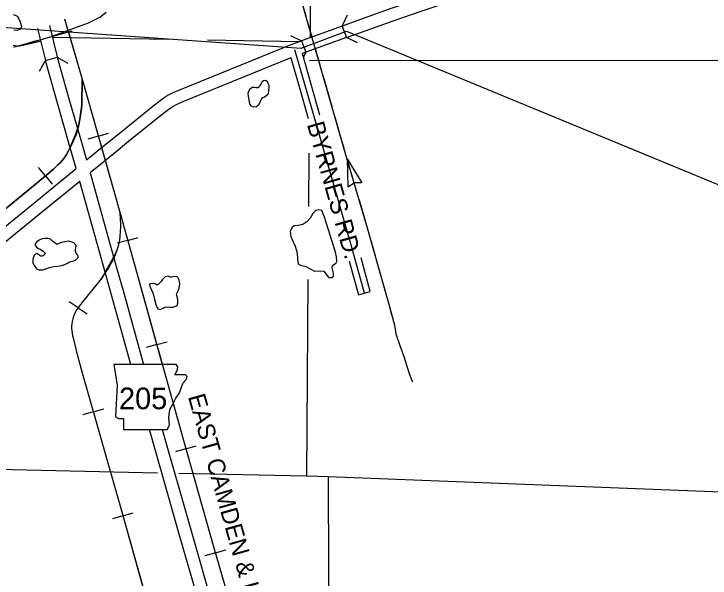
# Model space of a CAD drawing. Extents: x 1373094 to 1376427, y 1168361 to 1170494.
# Drawn here: x 1374665 to 1375232, y 1168831 to 1169290 of the extents above; entities that cross this region are included whole.
import ezdxf

# ---------------------------------------------------------------- set-up
doc = ezdxf.new("R2010")
doc.units = 0
for name, color, linetype in [('R_Axis', 7, 'Continuous'), ('R_Dimension', 7, 'Continuous'), ('R_Draft', 7, 'Continuous'), ('R_Water Annot', 7, 'Continuous')]:
    doc.layers.add(name, color=color, linetype=linetype)

msp = doc.modelspace()

# ---------------------------------------------------------------- linework, layer by layer
at = {"layer": 'R_Axis'}
for p, q in [((1374899.43, 1169267.75), (1374902.83, 1169258.34)), ((1374733.98, 1169190.12), (1374742.45, 1169192.52)), ((1374733.98, 1169190.12), (1374725.51, 1169187.73)), ((1374936.39, 1169171.79), (1374936.99, 1169148.91)), ((1374936.39, 1169171.79), (1374948.35, 1169152.28)), ((1374690.97, 1169157.88), (1374685.36, 1169164.66)), ((1374690.97, 1169157.88), (1374696.58, 1169151.1)), ((1374936.99, 1169148.91), (1374942.18, 1169152.1)), ((1374948.35, 1169152.28), (1374942.26, 1169152.12)), ((1374757.89, 1169105.43), (1374766.36, 1169107.81)), ((1374757.89, 1169105.43), (1374749.41, 1169103.06)), ((1374945.68, 1169061.27), (1374955.32, 1169063.92)), ((1374717.59, 1169050.61), (1374710.23, 1169055.44)), ((1374717.59, 1169050.61), (1374724.95, 1169045.79)), ((1374781.55, 1169020.67), (1374790.03, 1169023.04)), ((1374781.55, 1169020.67), (1374773.07, 1169018.31)), ((1374729.98, 1168966.05), (1374721.51, 1168963.64)), ((1374729.98, 1168966.05), (1374738.44, 1168968.45)), ((1374805.23, 1168935.92), (1374796.76, 1168933.52)), ((1374805.23, 1168935.92), (1374813.69, 1168938.32)), ((1374754.01, 1168881.4), (1374745.54, 1168879.01)), ((1374754.01, 1168881.4), (1374762.48, 1168883.78)), ((1374829.28, 1168851.27), (1374820.83, 1168848.82)), ((1374829.28, 1168851.27), (1374837.73, 1168853.72))]:
    msp.add_line(p, q, dxfattribs=at)
for points in [[(1374906.66, 1169411.1), (1374906.32, 1169269.99)], [(1374990.01, 1168990.5), (1374989.46, 1168991.36), (1374987.1, 1168997), (1374982.47, 1169011.56), (1374979.67, 1169019.8), (1374976.73, 1169028.3), (1374975.26, 1169036.23), (1374970.65, 1169053.39), (1374953.09, 1169115.44), (1374934.6, 1169177.81), (1374897.2, 1169307.95), (1374877.82, 1169376.24)], [(1375047.9, 1169319.87), (1374993.51, 1169301.24), (1374970.66, 1169293.33), (1374957.07, 1169288.57), (1374932.54, 1169279.71)], [(1374935.94, 1169270.3), (1374960.42, 1169279.14), (1374973.95, 1169283.89), (1374996.76, 1169291.79), (1375050.66, 1169310.25)], [(1374903.02, 1169287.69), (1374897.44, 1169307.09)], [(1374664.69, 1169289.18), (1374666.29, 1169288.66), (1374668.02, 1169287.73), (1374669.1, 1169286.14), (1374670.18, 1169283.61), (1374671.12, 1169281.48), (1374671.67, 1169279.08), (1374670.62, 1169277.07), (1374667.97, 1169276.12), (1374665.31, 1169276.24)], [(1374696.62, 1169271.37), (1374720.05, 1169280.03), (1374726.15, 1169282.2), (1374730.53, 1169284.49), (1374735.16, 1169286.79), (1374740.32, 1169290.96)], [(1374932.54, 1169279.71), (1374936.79, 1169288.76)], [(1374706.56, 1169285.51), (1374720.89, 1169236.39), (1374740.58, 1169166.79)], [(1374684.6, 1169277.69), (1374690.98, 1169251.63)], [(1374694.32, 1169280.16), (1374700.54, 1169254.61)], [(1374932.54, 1169279.71), (1374899.43, 1169267.75)], [(1374907.88, 1169270.8), (1374906.23, 1169276.52)], [(1374932.54, 1169279.71), (1374935.94, 1169270.3)], [(1374712.44, 1169275.44), (1374668.72, 1169263.46)], [(1374696.6, 1169270.79), (1374791.4, 1169269.11)], [(1374709.71, 1169274.71), (1374720.89, 1169236.39), (1374751.47, 1169128.32), (1374762.3, 1169089.68), (1374802.97, 1168943.89), (1374828.09, 1168855.37), (1374852.96, 1168769.72), (1374869.21, 1168714.06), (1374879.23, 1168680.09)], [(1374890.38, 1169272), (1374899.43, 1169267.75)], [(1374935.94, 1169270.3), (1374902.83, 1169258.34)], [(1374944.99, 1169266.05), (1374935.94, 1169270.3)], [(1374664.72, 1169264.08), (1374668.85, 1169263.44), (1374686.71, 1169267.52)], [(1374683.65, 1169267.55), (1374668.72, 1169263.46), (1374665.76, 1169262.65)], [(1374790.07, 1169223.1), (1374794.94, 1169225.57), (1374799.42, 1169227.47), (1374892.2, 1169265.14), (1374899.43, 1169267.75)], [(1374822.99, 1169268.55), (1374897.35, 1169267.23)], [(1374668.72, 1169263.46), (1374665.04, 1169262.45)], [(1374950.5, 1169062.6), (1374940.01, 1169100.71), (1374910.6, 1169202.25), (1374894.02, 1169260.48)], [(1374914.46, 1169247.89), (1374910.64, 1169261.17)], [(1374690.95, 1169251.75), (1374700.57, 1169254.48)], [(1374700.57, 1169254.48), (1374709.31, 1169249.61)], [(1374700.57, 1169254.48), (1374710.45, 1169219.73), (1374720.35, 1169185.34), (1374724.42, 1169170.81)], [(1374890.74, 1169253.75), (1374803.24, 1169218.23), (1374799.1, 1169216.48), (1374795.7, 1169214.79)], [(1374890.74, 1169253.75), (1374897.37, 1169230.46)], [(1374902.83, 1169258.34), (1374900.11, 1169257.36)], [(1374906.99, 1169233.2), (1374900.11, 1169257.36)], [(1374902.83, 1169258.34), (1374900.96, 1169254.36)], [(1374686.08, 1169243.02), (1374690.95, 1169251.75)], [(1374715.97, 1169163.91), (1374710.73, 1169182.61), (1374700.83, 1169216.98), (1374690.95, 1169251.75)], [(1374905.85, 1169251.57), (1375238.19, 1169252.01), (1375330.82, 1169249.65)], [(1374565.5, 1169055.01), (1374684.25, 1169152.32), (1374693.96, 1169160.35), (1374697.61, 1169163.43), (1374701.24, 1169166.75), (1374702.96, 1169168.49), (1374704.86, 1169170.54), (1374706.2, 1169172.23), (1374708.15, 1169175.22), (1374709.83, 1169178.3), (1374711.96, 1169182.54), (1374713.35, 1169185.4), (1374714.52, 1169187.99), (1374715.95, 1169191.55), (1374716.79, 1169194.11), (1374717.6, 1169197.04), (1374718.18, 1169199.53), (1374718.77, 1169202.46), (1374719.36, 1169205.68), (1374719.94, 1169209.63), (1374720.37, 1169213.11), (1374720.6, 1169215.54), (1374720.89, 1169236.39)], [(1374720.89, 1169236.39), (1374720.6, 1169215.54), (1374720.37, 1169213.11), (1374719.94, 1169209.63), (1374719.36, 1169205.68), (1374718.77, 1169202.46), (1374718.18, 1169199.53), (1374717.6, 1169197.04), (1374716.79, 1169194.11), (1374715.95, 1169191.55), (1374714.52, 1169187.99), (1374713.35, 1169185.4), (1374711.96, 1169182.54), (1374709.83, 1169178.3), (1374708.15, 1169175.22), (1374706.2, 1169172.23), (1374704.86, 1169170.54), (1374702.96, 1169168.49), (1374701.24, 1169166.75), (1374697.61, 1169163.43), (1374693.96, 1169160.35), (1374684.25, 1169152.32), (1374565.5, 1169055.01)], [(1374720.89, 1169236.39), (1374720.6, 1169215.54), (1374720.37, 1169213.11), (1374719.94, 1169209.63), (1374719.36, 1169205.68), (1374718.82, 1169202.71)], [(1374924.18, 1169214.06), (1374916.89, 1169239.43)], [(1374872.35, 1169224.74), (1374872.76, 1169227.07), (1374872.91, 1169230.22), (1374872.95, 1169231.42), (1374872.26, 1169233.01), (1374871.57, 1169234.4), (1374870.29, 1169235.45), (1374868.5, 1169235.09), (1374866.99, 1169234), (1374866.4, 1169233.12), (1374865.37, 1169231.37), (1374864.92, 1169230.29), (1374863.87, 1169229.34), (1374862.27, 1169229.51), (1374861.07, 1169229.83), (1374859.54, 1169229.81), (1374857.3, 1169228.5), (1374856.14, 1169226.35), (1374855.69, 1169224.87), (1374856.06, 1169222.8), (1374856.45, 1169219.74), (1374856.68, 1169217.74), (1374857.31, 1169215.88), (1374858.19, 1169214.82), (1374860.6, 1169213.92), (1374862.8, 1169214.16), (1374864.89, 1169216.13), (1374865.85, 1169218.55), (1374866.69, 1169220.23), (1374867.8, 1169221.52), (1374868.59, 1169221.93), (1374870.04, 1169222.82), (1374871.88, 1169224.25), (1374872.35, 1169224.74)], [(1374897.37, 1169230.46), (1374904.75, 1169204.55)], [(1374914.36, 1169207.33), (1374906.99, 1169233.2)], [(1374724.42, 1169170.81), (1374740.53, 1169183.95), (1374752.34, 1169193.55), (1374778.37, 1169214.5), (1374780.84, 1169216.39), (1374785.5, 1169220), (1374788.48, 1169222.05), (1374790.36, 1169223.26)], [(1374795.38, 1169214.61), (1374794.02, 1169213.73), (1374791.41, 1169211.93), (1374786.94, 1169208.46), (1374784.54, 1169206.63), (1374758.63, 1169185.77), (1374746.84, 1169176.2), (1374727.37, 1169160.3)], [(1374718.82, 1169202.71), (1374717.69, 1169198.36), (1374715.09, 1169191.07), (1374712.88, 1169185.22), (1374710.15, 1169178.84), (1374708.15, 1169175.22), (1374706.2, 1169172.23), (1374704.86, 1169170.54), (1374702.96, 1169168.49), (1374701.24, 1169166.75), (1374697.61, 1169163.43), (1374693.96, 1169160.35), (1374684.25, 1169152.32), (1374565.5, 1169055.01), (1374470.65, 1168977.12), (1374440.83, 1168952.74)], [(1374930.26, 1169192.92), (1374926.61, 1169205.6)], [(1374933.91, 1169180.23), (1374930.26, 1169192.92)], [(1374905.32, 1169176.44), (1374905.02, 1169132.9)], [(1374943.89, 1169146.47), (1374936.39, 1169171.79)], [(1374540.38, 1169020.57), (1374624.4, 1169089.36), (1374681.19, 1169135.53), (1374715.97, 1169163.91)], [(1374740.58, 1169166.79), (1374751.47, 1169128.32), (1374762.3, 1169089.68), (1374786.05, 1169004.54)], [(1374727.37, 1169160.3), (1374749.24, 1169082.3), (1374754.2, 1169064.61), (1374770.91, 1169004.55)], [(1374718.92, 1169153.41), (1374687.5, 1169127.78), (1374630.73, 1169081.61), (1374546.71, 1169012.83)], [(1374760.52, 1169004.55), (1374744.57, 1169061.92), (1374739.62, 1169079.6), (1374718.92, 1169153.41)], [(1374953.86, 1169112.72), (1374953.09, 1169115.44), (1374946.39, 1169138.04)], [(1374927.86, 1169087.38), (1374927.95, 1169088.44), (1374927.69, 1169091.98), (1374926.89, 1169095.97), (1374917.95, 1169124.42), (1374915.8, 1169129.8), (1374913.53, 1169130.17), (1374910.95, 1169129.59), (1374908.59, 1169127.42), (1374906.26, 1169123.44), (1374903.71, 1169120.6), (1374900.42, 1169118.27), (1374896.57, 1169117.54), (1374893.45, 1169117.16), (1374891.35, 1169115.59), (1374890.13, 1169112.7), (1374890.6, 1169108.5), (1374892.26, 1169104.85), (1374894.2, 1169100.74), (1374895.68, 1169095.42), (1374896.18, 1169089.95), (1374896.64, 1169086.28), (1374898.65, 1169085.25), (1374902.86, 1169084.24), (1374906.82, 1169082.1), (1374909.85, 1169080.28), (1374913.64, 1169080.67), (1374917.43, 1169080.53), (1374919.47, 1169077.89), (1374919.82, 1169077.16), (1374920.97, 1169075.71), (1374921.58, 1169075.38), (1374924.04, 1169075.29), (1374924.96, 1169075.97), (1374925.42, 1169076.31), (1374925.26, 1169078.31), (1374925.03, 1169079.98), (1374924.6, 1169081.84), (1374924.3, 1169083.64), (1374924.48, 1169084.58), (1374925.46, 1169085.66), (1374926.32, 1169086.28), (1374927.17, 1169086.83), (1374927.86, 1169087.38)], [(1374751.47, 1169128.32), (1374751.93, 1169122.31), (1374752.05, 1169118.61), (1374752.05, 1169116.32), (1374751.66, 1169108.88), (1374751.29, 1169105.91), (1374750.83, 1169103.06), (1374750.29, 1169100.74), (1374749.38, 1169098.16), (1374748.68, 1169096.21), (1374747.73, 1169093.79), (1374746, 1169089.76), (1374744.58, 1169087.13), (1374742.25, 1169083.15), (1374740.69, 1169080.66), (1374735.37, 1169072.69), (1374720.24, 1169054.29), (1374718.1, 1169051.38), (1374716.07, 1169048.3), (1374715.25, 1169046.89), (1374714.66, 1169045.65), (1374713.9, 1169043.48), (1374713.31, 1169041.54), (1374712.84, 1169039.42), (1374712.54, 1169037.67), (1374712.37, 1169035.72), (1374712.33, 1169033.92), (1374712.43, 1169032.07), (1374712.66, 1169030.19), (1374713.1, 1169027.86), (1374713.46, 1169026.19), (1374716.39, 1169014.75), (1374721, 1168997.65), (1374753.05, 1168884.79), (1374789.66, 1168754.64)], [(1374751.47, 1169128.32), (1374751.93, 1169122.31), (1374752.05, 1169118.61), (1374752.05, 1169116.32), (1374751.66, 1169108.88), (1374751.29, 1169105.91), (1374750.83, 1169103.06), (1374750.29, 1169100.74), (1374749.38, 1169098.16), (1374748.75, 1169096.4)], [(1374717.19, 1169093.64), (1374716.98, 1169093.97), (1374716.1, 1169095.16), (1374715.61, 1169096.42), (1374715.52, 1169097.76), (1374715.89, 1169099.3), (1374715.93, 1169101.17), (1374715.51, 1169102.17), (1374714.16, 1169103.41), (1374712.82, 1169103.99), (1374709.88, 1169104.68), (1374706.89, 1169104.3), (1374704.17, 1169103.66), (1374702.06, 1169102.76), (1374700.41, 1169102.2), (1374698.86, 1169103.04), (1374696.9, 1169104.68), (1374695.14, 1169106.52), (1374692.94, 1169107.09), (1374690.41, 1169107.05), (1374688.42, 1169106.62), (1374686.04, 1169105.65), (1374684.06, 1169104.35), (1374682.56, 1169102.59), (1374682.58, 1169101.45), (1374683.95, 1169099.54), (1374685.42, 1169098.76), (1374687.17, 1169097.98), (1374689.25, 1169096.75), (1374690.13, 1169095.96), (1374690.75, 1169094.9), (1374690.49, 1169094.09), (1374689.58, 1169093.08), (1374688.46, 1169092.53), (1374687.39, 1169092.58), (1374686.58, 1169093.23), (1374684.1, 1169094.66), (1374682.97, 1169094.18), (1374682.12, 1169093.3), (1374681.15, 1169091.61), (1374680.72, 1169089.4), (1374680.89, 1169087.53), (1374681.79, 1169085.07), (1374683.09, 1169083.02), (1374683.9, 1169082.37), (1374685.65, 1169081.53), (1374686.92, 1169081.35), (1374688.98, 1169081.45), (1374692.09, 1169082.43), (1374694.4, 1169083.47), (1374697.65, 1169084.32), (1374700.84, 1169084.5), (1374704.09, 1169085.09), (1374706.94, 1169085.93), (1374708.91, 1169087.03), (1374710.69, 1169088), (1374713.81, 1169088.78), (1374715.4, 1169089.47), (1374716.31, 1169090.22), (1374717.23, 1169091.1), (1374717.62, 1169091.44), (1374717.61, 1169092.38), (1374717.4, 1169093.04), (1374717.19, 1169093.64)], [(1374963.44, 1169078.85), (1374956.26, 1169104.25)], [(1374748.75, 1169096.4), (1374744.37, 1169088.17), (1374740.52, 1169081.1), (1374737.42, 1169075.64), (1374736.35, 1169073.93), (1374735.37, 1169072.69), (1374720.24, 1169054.29), (1374718.1, 1169051.38), (1374716.07, 1169048.3), (1374715.25, 1169046.89), (1374714.66, 1169045.65), (1374713.9, 1169043.48), (1374713.31, 1169041.54), (1374712.84, 1169039.42), (1374712.54, 1169037.67), (1374712.37, 1169035.72), (1374712.33, 1169033.92), (1374712.43, 1169032.07), (1374712.66, 1169030.19), (1374713.1, 1169027.86), (1374713.46, 1169026.19), (1374716.39, 1169014.75), (1374721, 1168997.65), (1374753.05, 1168884.79), (1374782.56, 1168779.89)], [(1374955.32, 1169063.92), (1374947.78, 1169091.31)], [(1374938.14, 1169088.65), (1374945.68, 1169061.27)], [(1374775.74, 1169069.92), (1374776.02, 1169068.21), (1374778.79, 1169061.97), (1374779.87, 1169057.31), (1374780.87, 1169053.19), (1374781.57, 1169051.06), (1374782.59, 1169049.81), (1374784.26, 1169049.23), (1374786.71, 1169050.21), (1374788.22, 1169051.03), (1374789.88, 1169051.53), (1374792.41, 1169051.23), (1374794.74, 1169051.2), (1374796.27, 1169051.56), (1374798.18, 1169052.46), (1374798.68, 1169054.27), (1374798.85, 1169056.34), (1374798.47, 1169058.81), (1374797.91, 1169060.67), (1374797.63, 1169061.8), (1374798.66, 1169063.82), (1374799.81, 1169066.51), (1374800.35, 1169070.13), (1374799.69, 1169073.39), (1374798.94, 1169074.85), (1374798.25, 1169075.84), (1374795.99, 1169076), (1374793.73, 1169075.5), (1374792.47, 1169075.55), (1374790.92, 1169076.39), (1374788.34, 1169075.88), (1374787.03, 1169074.46), (1374786.05, 1169073.38), (1374785.07, 1169072.02), (1374783.9, 1169070.54), (1374782.85, 1169069.59), (1374782, 1169069.1), (1374781.06, 1169069.42), (1374779.98, 1169070.08), (1374777.98, 1169070.31), (1374776.45, 1169070.22), (1374775.74, 1169069.92)], [(1374904.61, 1169073.62), (1374903.5, 1168913.86)], [(1374972.92, 1169044.95), (1374970.65, 1169053.39), (1374965.84, 1169070.38)], [(1374982.59, 1169011.17), (1374982.47, 1169011.56), (1374979.67, 1169019.8), (1374976.73, 1169028.3), (1374975.26, 1169036.23), (1374975.2, 1169036.45)], [(1374990.01, 1168990.5), (1374989.46, 1168991.36), (1374987.1, 1168997), (1374985.26, 1169002.78)], [(1374794.92, 1168972.72), (1374802.97, 1168943.89), (1374828.09, 1168855.37), (1374852.96, 1168769.72), (1374869.21, 1168714.06), (1374880.32, 1168676.41)], [(1374818.41, 1168802), (1374799.86, 1168866.56), (1374775.69, 1168951.55)], [(1374786.09, 1168951.55), (1374809.47, 1168869.31), (1374827.26, 1168807.44)], [(1374460.31, 1168922.17), (1374546.33, 1168921.45), (1374569.16, 1168921.2), (1374782.18, 1168916.53)], [(1374799.62, 1168916.14), (1374903.5, 1168913.86), (1374921.14, 1168913.33), (1375240.86, 1168901.02), (1375253.71, 1168900.55), (1375428.35, 1168895.68)], [(1374921.14, 1168913.33), (1374921.89, 1168680.08)]]:
    msp.add_lwpolyline(points, dxfattribs=at)
msp.add_lwpolyline([(1374746.74, 1169004.56), (1374749.28, 1168987.64), (1374748.15, 1168961.98), (1374750.4, 1168960.57), (1374754.63, 1168960.57), (1374754.63, 1168951.55), (1374790.16, 1168951.55), (1374791.85, 1168955.21), (1374791.29, 1168961.13), (1374792.13, 1168967.9), (1374795.24, 1168973.26), (1374797.21, 1168977.21), (1374800.03, 1168981.44), (1374801.72, 1168985.95), (1374803.13, 1168989.61), (1374805.67, 1168992.71), (1374806.23, 1168994.69), (1374805.1, 1168996.1), (1374796.36, 1168996.1), (1374798.34, 1169000.05), (1374798.62, 1169002.58), (1374797.45, 1169004.53)], close=True, dxfattribs=at)
at = {"layer": 'R_Dimension'}
for p, q in [((1373948.3, 1169328.7), (1374899.05, 1169261.78)), ((1374935.89, 1169275.48), (1375606.99, 1168998.81))]:
    msp.add_line(p, q, dxfattribs=at)
at = {"layer": 'R_Draft'}
msp.add_line((1374899.05, 1169261.78), (1374935.89, 1169275.48), dxfattribs=at)

# ---------------------------------------------------------------- texts
at = {"layer": 'R_Axis'}
msp.add_text('205', height=17.6, dxfattribs=at).set_placement((1374750.87, 1168968.14))
at = {"layer": 'R_Water Annot'}
for s, p in [('BYRNES RD.', (1374903.64, 1169199.85)), ('EAST CAMDEN & HIGHLAND R.R.', (1374806.86, 1168978.46))]:
    msp.add_text(s, height=14.08, rotation=285.7868, dxfattribs=at).set_placement(p)

doc.saveas('drawing.dxf')
